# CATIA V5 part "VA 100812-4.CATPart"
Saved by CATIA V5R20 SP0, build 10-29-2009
Part number: VA 100812-4
Revision: ANY
Definition: UNKNOWN
Nomenclature: VA 100812-4
Source: Unknown
Bounding box of the stored display mesh (mm): x -3.012 to 3.012, y 0 to 5.3, z -2.75 to 2.75
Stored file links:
  C:\Users\Utente\Desktop\IO LAVORO\3D X SITO CF\CUMSA\3D files VA\VA 100812\VA 100812-4.CATPart
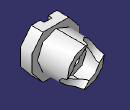
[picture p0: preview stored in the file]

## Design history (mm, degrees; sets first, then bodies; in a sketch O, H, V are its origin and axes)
Body1 "Cortar-Extruir4" (main body)
  Solid1: solid without history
